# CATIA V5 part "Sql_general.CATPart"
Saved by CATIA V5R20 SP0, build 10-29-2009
Part number: Sql_general
Publications: "Plan ref", "Point A", "Point D", "Point B", "Point C", "Longueur de la barre 1"
Bounding box of the stored display mesh (mm): x 0 to 72.915, y 0 to 72.915, z 0 to 0
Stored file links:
  C:\Users\Admin\Desktop\IAO\Sql_general.CATPart
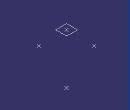
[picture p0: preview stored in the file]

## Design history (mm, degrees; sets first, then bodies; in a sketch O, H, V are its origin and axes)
Parameters
  `Longueur de la barre 1` = 40 mm
Set1
  Plane1 "Plan ref": type Offset, RefPlane xy-plane, Offset 0
  Point1 "Point A": (0, 0, 0)
  Point2 "Point D": (40 {= `Longueur de la barre 1`}, 0, 0)
  Point3 "Point B": (0, 40 {= `Longueur de la barre 1`}, 0)
  Point4 "Point C": (72.915 {= ((2+sqrt(28) )/4)*`Longueur de la barre 1`}, 72.915 {= ((2+sqrt(28) )/4)*`Longueur de la barre 1`}, 0)
Body1 (main body)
